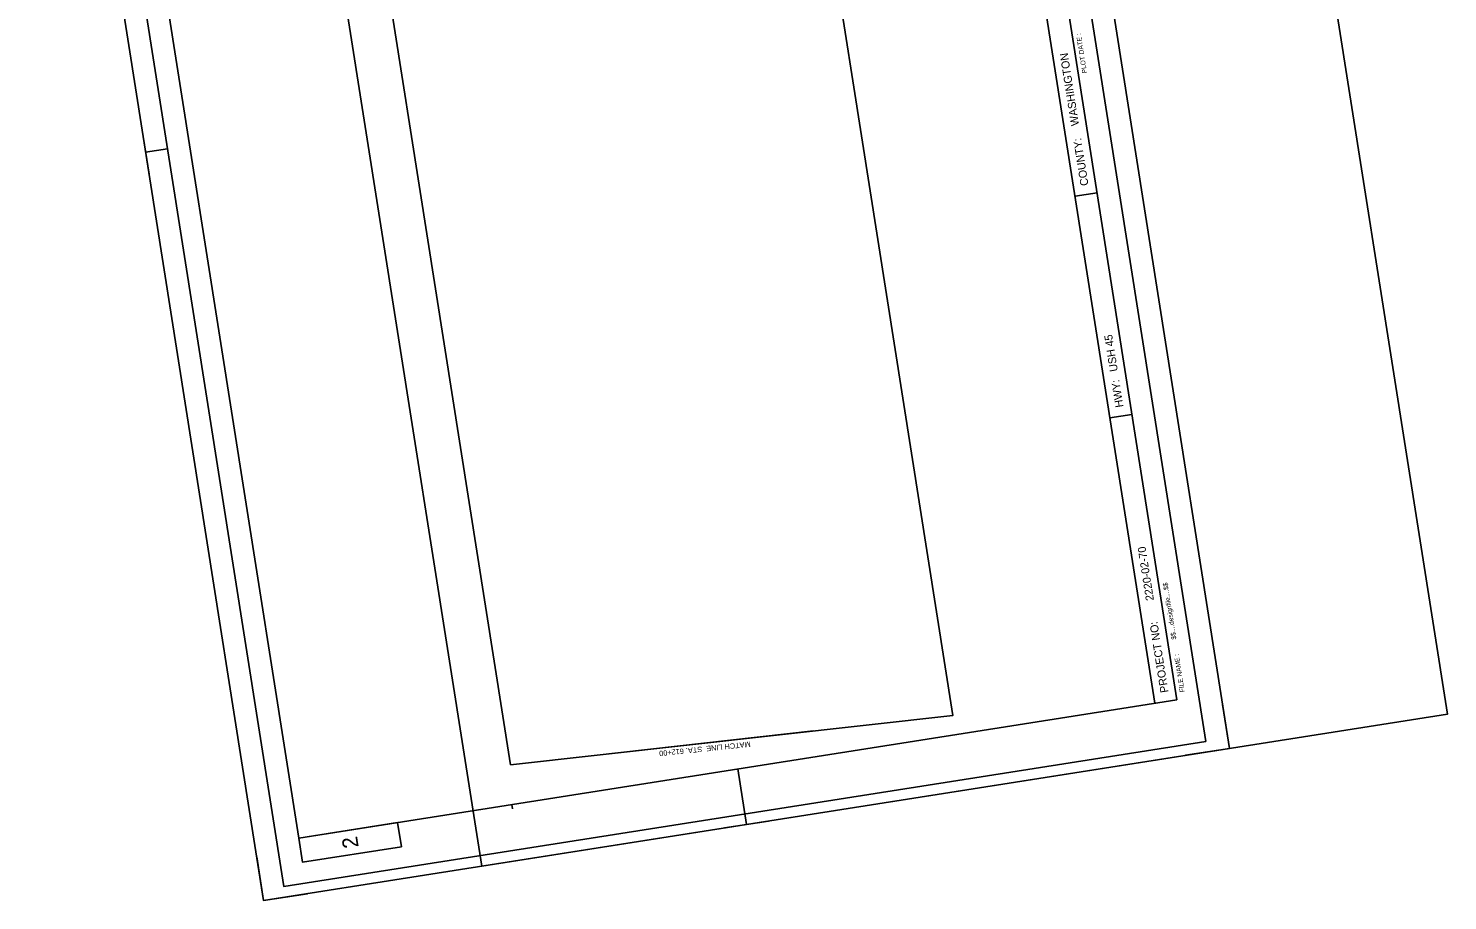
# Model space of a CAD drawing. Extents: x 355094 to 356691, y 183238 to 185127.
# Drawn here: x 355094 to 356691, y 183238 to 184219 of the extents above; entities that cross this region are included whole.
import ezdxf

# ---------------------------------------------------------------- set-up
doc = ezdxf.new("R2010")
doc.units = 0
for name, color, linetype in [('Default', 7, 'Continuous'), ('P_TXT_Plan 1 [KAPUR_CADDS_LEVELS]', 7, 'Continuous'), ('P_TXT_Plan 2 [KAPUR_CADDS_LEVELS]', 7, 'Continuous'), ('P_TXT_Plan 3 [KAPUR_CADDS_LEVELS]', 7, 'Continuous'), ('P_TXT_Plan 4 [KAPUR_CADDS_LEVELS]', 7, 'Continuous'), ('P_TXT_Plan 4_TEXT [KAPUR_CADDS_LEVELS]', 7, 'Continuous'), ('PLT_Sheet_Info', 7, 'Continuous')]:
    doc.layers.add(name, color=color, linetype=linetype)

msp = doc.modelspace()

# ---------------------------------------------------------------- linework, layer by layer
at = {"layer": 'Default'}
msp.add_lwpolyline([(355636.6, 183390.5), (356134.1, 183446), (355900.3, 184929.2), (355402.9, 184873.7)], close=True, dxfattribs=at)
msp.add_lwpolyline([(355636.6, 183390.5), (356134.1, 183446), (355900.3, 184929.2), (355402.9, 184873.7)], close=True, dxfattribs=at)
msp.add_lwpolyline([(355636.6, 183390.5), (356134.1, 183446), (355900.3, 184929.2), (355402.9, 184873.7)], close=True, dxfattribs=at)
msp.add_lwpolyline([(355636.6, 183390.5), (356134.1, 183446), (355900.3, 184929.2), (355402.9, 184873.7)], close=True, dxfattribs=at)
msp.add_lwpolyline([(355636.6, 183390.5), (356134.1, 183446), (355900.3, 184929.2), (355402.9, 184873.7)], close=True, dxfattribs=at)
at = {"layer": 'P_TXT_Plan 1 [KAPUR_CADDS_LEVELS]'}
for p, q in [((356361.4, 183459.6), (356116.2, 185015.4)), ((356386.1, 183463.5), (356140.9, 185019.3)), ((355398.3, 183307.8), (355153.1, 184863.6)), ((355229.9, 184055), (355222.1, 184104.4)), ((355226, 184079.7), (355250.7, 184083.6)), ((356296.2, 184034), (356271.5, 184030.1)), ((356335.5, 183784.6), (356310.8, 183780.7)), ((356386.1, 183463.5), (355398.3, 183307.8)), ((356445.3, 183408.8), (356437.5, 183458.2)), ((355886.4, 183422.7), (355886.4, 183422.7)), ((356445.3, 183408.8), (356395.9, 183401.1)), ((355902, 183323.2), (355892.2, 183385.7)), ((355637.8, 183345.6), (355638.6, 183340.7)), ((355926.7, 183327.1), (355877.3, 183319.3)), ((355358.7, 183237.6), (355351, 183287)), ((355408.1, 183245.4), (355358.7, 183237.6))]:
    msp.add_line(p, q, dxfattribs=at)
msp.add_lwpolyline([(355398.3, 183307.8), (355402.6, 183280.7), (355513.7, 183298.2), (355509.4, 183325.4)], close=True, dxfattribs=at)
at = {"layer": 'P_TXT_Plan 2 [KAPUR_CADDS_LEVELS]'}
for points in [[(356445.3, 183408.8), (356180.7, 185088.1), (355094.1, 184916.8), (355358.7, 183237.6)], [(356418.8, 183416.8), (356161.1, 185051.6), (355123.9, 184888.1), (355381.6, 183253.3)]]:
    msp.add_lwpolyline(points, close=True, dxfattribs=at)
at = {"layer": 'P_TXT_Plan 4 [KAPUR_CADDS_LEVELS]'}
msp.add_line((355730.4, 183401), (355977.4, 183428.5), dxfattribs=at)
at = {"layer": 'P_TXT_Plan 4_TEXT [KAPUR_CADDS_LEVELS]'}
msp.add_lwpolyline([(355358.7, 183237.6), (355094.1, 184916.8), (356180.7, 185088.1), (356445.3, 183408.8)], close=True, dxfattribs=at)
at = {"layer": 'PLT_Sheet_Info'}
msp.add_lwpolyline([(355604, 183276.2), (355339.3, 184955.5), (356425.9, 185126.8), (356690.6, 183447.5), (355604, 183276.2)], dxfattribs=at)

# ---------------------------------------------------------------- texts
at = {"layer": 'P_TXT_Plan 1 [KAPUR_CADDS_LEVELS]'}
for s, height, p in [('PLOT DATE :', 5.4, (356285, 184168.9)), (' WASHINGTON', 9, (356276.6, 184106.8)), ('COUNTY:', 9, (356286.7, 184042.6)), (' USH 45', 9, (356320.2, 183830.2)), ('HWY:', 9, (356326, 183793.2)), (' 2220-02-70', 9, (356360.8, 183572.4)), ('$$....designfile....$$', 5.4, (356385.5, 183531.8)), ('PROJECT NO:', 9, (356376.6, 183472.2)), ('FILE NAME :', 5.4, (356394.8, 183472.5)), ('2', 17.5, (355465.7, 183297.9))]:
    msp.add_text(s, height=height, rotation=98.957, dxfattribs=at).set_placement(p)
at = {"layer": 'P_TXT_Plan 3 [KAPUR_CADDS_LEVELS]'}
msp.add_text('MATCH LINE  STA. 612+00', height=6, rotation=185.9528, dxfattribs=at).set_placement((355906.2, 183416.7))

doc.saveas('drawing.dxf')
